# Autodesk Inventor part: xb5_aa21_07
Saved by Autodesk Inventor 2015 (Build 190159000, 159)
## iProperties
Created: 2018-05
Part Number: xb5_aa21_07
Checked By: TraceParts S.A.
Material: Generic
Catalog Web Link: www.traceparts.com
Document SubType Name: Modeling
Designer: TraceParts
Density: 1 g/cm^3
Appearance: Default
Company: TraceParts S.A.
Author: TraceParts
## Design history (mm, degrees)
feature "xb5_aa21_07.ipt"
body "Solid1"
